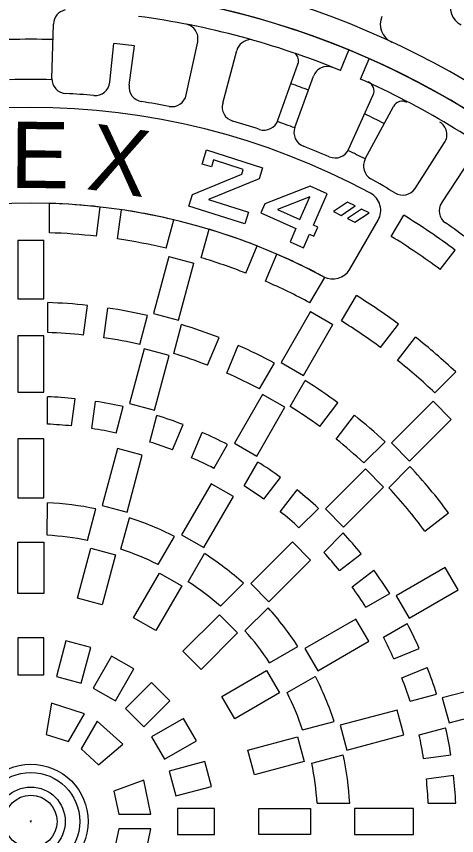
# Model space of a CAD drawing. Extents: x -7.1 to 10, y -5 to 6.
# Drawn here: x -4.588 to -4.121, y 0.707 to 1.576 of the extents above; entities that cross this region are included whole.
import ezdxf

# ---------------------------------------------------------------- set-up
doc = ezdxf.new("R2010")
doc.units = 0
doc.layers.add('Level 1', color=7, linetype='Continuous')

# ---------------------------------------------------------------- blocks, each defined once
blk = doc.blocks.new('CRAN')
at = {"layer": 'Level 1'}
for p, q in [((-3.652, 6.599), (-1.391, 7.083)), ((-3.232, 4.178), (-1.568, 4.4)), ((-1.568, 4.4), (-1.47, 3.52)), ((-3.114, 3.352), (-1.47, 3.52)), ((-2.949, 0.9), (-0.638, 0.965)), ((-2.949, -0.892), (-0.638, -0.957)), ((-3.114, -3.345), (-1.471, -3.52)), ((-1.568, -4.392), (-1.47, -3.512)), ((-3.232, -4.17), (-1.568, -4.392)), ((-3.652, -6.592), (-1.391, -7.076))]:
    blk.add_line(p, q, dxfattribs=at)
for centre, radius, start, end in [((-1.26, 6.472), 0.625, 11.0144, 102.0722), ((-3.521, 5.988), 0.625, 102.0722, 190.9368), ((-34.491, 0.004), 30.918, 8.7409, 10.9368), ((-3.315, 4.797), 0.625, 188.7409, 277.6056), ((-3.048, 2.731), 0.625, 96.0776, 184.9422), ((-34.473, 0.013), 30.918, 2.7463, 4.9422), ((-2.967, 1.524), 0.625, 182.7463, 271.611), ((-0.656, 1.589), 0.625, 271.611, 348.8242), ((-2.967, -1.517), 0.625, 88.389, 177.2537), ((-0.656, -1.582), 0.625, 11.1758, 88.389), ((-34.473, -0.006), 30.918, 355.0578, 357.2537), ((-3.048, -2.723), 0.625, 175.0578, 263.9224), ((-3.315, -4.79), 0.625, 82.3944, 171.2591), ((-34.491, 0.004), 30.918, 349.0632, 351.2591), ((-3.521, -5.981), 0.625, 169.0632, 257.9278), ((-1.26, -6.464), 0.625, 257.9278, 348.9856)]:
    blk.add_arc(centre, radius, start, end, dxfattribs=at)

msp = doc.modelspace()

# ---------------------------------------------------------------- linework, layer by layer
at = {"layer": 'Level 1'}
for p, q in [((-4.55009, 1.51031), (-4.54846, 1.56809)), ((-4.4076, 1.49275), (-4.39551, 1.54927)), ((-4.48878, 1.50619), (-4.48441, 1.54728)), ((-4.46259, 1.54485), (-4.48459, 1.5473)), ((-4.46814, 1.50325), (-4.46259, 1.54485)), ((-4.36899, 1.48413), (-4.35397, 1.53995)), ((-4.24409, 1.51875), (-4.23516, 1.54042)), ((-4.22297, 1.50971), (-4.21346, 1.53114)), ((-4.31032, 1.46587), (-4.28915, 1.52559)), ((-4.29245, 1.45828), (-4.27271, 1.51261)), ((-4.23555, 1.43507), (-4.20935, 1.49276)), ((-4.21784, 1.42485), (-4.18778, 1.48062)), ((-4.16493, 1.39361), (-4.13363, 1.4422)), ((-4.55279, 1.34647), (-4.5525, 1.37772)), ((-4.50287, 1.34289), (-4.49879, 1.37388)), ((-4.48041, 1.33996), (-4.47622, 1.37093)), ((-4.19015, 1.34266), (-4.17692, 1.3651)), ((-4.42893, 1.33007), (-4.42076, 1.36025)), ((-4.23411, 1.30787), (-4.20415, 1.35976)), ((-4.39178, 1.32008), (-4.38341, 1.3502)), ((-4.58616, 1.33881), (-4.58616, 1.2763)), ((-4.58616, 1.33881), (-4.55882, 1.33881)), ((-4.55882, 1.2763), (-4.55882, 1.33881)), ((-4.55882, 1.2763), (-4.55882, 1.33881)), ((-4.34449, 1.3037), (-4.33253, 1.33258)), ((-4.32355, 1.29506), (-4.31149, 1.32389)), ((-4.13823, 1.30753), (-4.12238, 1.32819)), ((-4.426, 1.32133), (-4.44218, 1.26094)), ((-4.426, 1.32133), (-4.39958, 1.31425)), ((-4.41577, 1.25386), (-4.39958, 1.31425)), ((-4.41577, 1.25386), (-4.39958, 1.31425)), ((-4.27638, 1.27218), (-4.26068, 1.29922)), ((-4.24309, 1.25293), (-4.22721, 1.27985)), ((-4.58616, 1.2763), (-4.55882, 1.2763)), ((-4.55457, 1.24066), (-4.5545, 1.27245)), ((-4.51666, 1.23796), (-4.51251, 1.26947)), ((-4.49496, 1.23515), (-4.49082, 1.26665)), ((-4.44218, 1.26094), (-4.41577, 1.25386)), ((-4.27581, 1.26298), (-4.30707, 1.20884)), ((-4.27581, 1.26298), (-4.25213, 1.24931)), ((-4.45683, 1.22792), (-4.44861, 1.25863)), ((-4.42088, 1.21834), (-4.41259, 1.24903)), ((-4.28339, 1.19517), (-4.25213, 1.24931)), ((-4.28339, 1.19517), (-4.25213, 1.24931)), ((-4.20164, 1.22486), (-4.18262, 1.24966)), ((-4.58616, 1.23722), (-4.58616, 1.1773)), ((-4.55882, 1.23722), (-4.58616, 1.23722)), ((-4.55882, 1.1773), (-4.55882, 1.23722)), ((-4.38496, 1.20592), (-4.3728, 1.23528)), ((-4.18366, 1.2111), (-4.16455, 1.23582)), ((-4.36474, 1.19759), (-4.35258, 1.22695)), ((-4.45229, 1.2232), (-4.4678, 1.16532)), ((-4.42588, 1.21612), (-4.45229, 1.2232)), ((-4.44139, 1.15824), (-4.42588, 1.21612)), ((-4.30707, 1.20884), (-4.28339, 1.19517)), ((-4.32978, 1.18074), (-4.31388, 1.20828)), ((-4.14402, 1.17679), (-4.12185, 1.19884)), ((-4.29753, 1.16218), (-4.28158, 1.18968)), ((-4.58616, 1.1773), (-4.55882, 1.1773)), ((-4.32661, 1.175), (-4.35657, 1.12311)), ((-4.30293, 1.16133), (-4.32661, 1.175)), ((-4.55477, 1.14338), (-4.55471, 1.17251)), ((-4.52935, 1.14155), (-4.52555, 1.17041)), ((-4.50766, 1.13875), (-4.50386, 1.1676)), ((-4.4678, 1.16532), (-4.44139, 1.15824)), ((-4.26605, 1.14089), (-4.2467, 1.1661)), ((-4.14585, 1.16776), (-4.19005, 1.12355)), ((-4.14585, 1.16776), (-4.12651, 1.14842)), ((-4.48202, 1.13394), (-4.47448, 1.16208)), ((-4.33289, 1.10944), (-4.30293, 1.16133)), ((-4.44625, 1.12443), (-4.43866, 1.15255)), ((-4.24867, 1.12761), (-4.22932, 1.15282)), ((-4.17072, 1.10421), (-4.12651, 1.14842)), ((-4.17072, 1.10421), (-4.12651, 1.14842)), ((-4.42218, 1.11608), (-4.41104, 1.14297)), ((-4.40195, 1.10776), (-4.39081, 1.13465)), ((-4.58616, 1.1278), (-4.58616, 1.06526)), ((-4.55882, 1.1278), (-4.58616, 1.1278)), ((-4.55882, 1.06526), (-4.55882, 1.1278)), ((-4.37842, 1.09648), (-4.36386, 1.12171)), ((-4.35657, 1.12311), (-4.33289, 1.10944)), ((-4.21926, 1.10228), (-4.19678, 1.12476)), ((-4.19005, 1.12355), (-4.17072, 1.10421)), ((-4.48061, 1.1175), (-4.4968, 1.05709)), ((-4.4542, 1.11042), (-4.48061, 1.1175)), ((-4.47039, 1.05001), (-4.4542, 1.11042)), ((-4.34634, 1.07804), (-4.33173, 1.10323)), ((-4.21768, 1.09592), (-4.26005, 1.05355)), ((-4.19835, 1.07658), (-4.21768, 1.09592)), ((-4.19291, 1.07601), (-4.17039, 1.09844)), ((-4.32525, 1.06374), (-4.30753, 1.08683)), ((-4.38132, 1.08024), (-4.41259, 1.02607)), ((-4.35764, 1.06656), (-4.38132, 1.08024)), ((-4.30786, 1.05047), (-4.29014, 1.07356)), ((-4.24072, 1.03421), (-4.19835, 1.07658)), ((-4.58616, 1.06526), (-4.55882, 1.06526)), ((-4.38891, 1.0124), (-4.35764, 1.06656)), ((-4.55501, 1.02552), (-4.55494, 1.0601)), ((-4.51253, 1.02006), (-4.50358, 1.05348)), ((-4.4968, 1.05709), (-4.47039, 1.05001)), ((-4.28805, 1.03349), (-4.26746, 1.05408)), ((-4.26005, 1.05355), (-4.24072, 1.03421)), ((-4.47699, 1.01065), (-4.46797, 1.04403)), ((-4.15466, 1.02997), (-4.12945, 1.04931)), ((-4.41259, 1.02607), (-4.38891, 1.0124)), ((-4.26184, 1.00737), (-4.2412, 1.02792)), ((-4.58616, 0.96358), (-4.58616, 1.01834)), ((-4.58616, 1.01834), (-4.55882, 1.01834)), ((-4.55882, 1.01834), (-4.55882, 0.96358)), ((-4.43738, 0.99437), (-4.42008, 1.02434)), ((-4.29506, 1.01854), (-4.33928, 0.97432)), ((-4.27572, 0.99921), (-4.29506, 1.01854)), ((-4.52311, 0.95888), (-4.50894, 1.01177)), ((-4.50894, 1.01177), (-4.48253, 1.00469)), ((-4.48253, 1.00469), (-4.4967, 0.9518)), ((-4.40548, 0.97609), (-4.38813, 1.006)), ((-4.24517, 0.98809), (-4.22207, 1.00582)), ((-4.31995, 0.95499), (-4.27572, 0.99921)), ((-4.13294, 0.99134), (-4.18483, 0.96138)), ((-4.11927, 0.96766), (-4.13294, 0.99134)), ((-4.46343, 0.93802), (-4.43605, 0.98544)), ((-4.43605, 0.98544), (-4.41237, 0.97177)), ((-4.2318, 0.97077), (-4.20871, 0.98849)), ((-4.37143, 0.95012), (-4.34696, 0.97458)), ((-4.33928, 0.97432), (-4.31995, 0.95499)), ((-4.41237, 0.97177), (-4.43975, 0.92435)), ((-4.17116, 0.9377), (-4.11927, 0.96766)), ((-4.55882, 0.96358), (-4.58616, 0.96358)), ((-4.4967, 0.9518), (-4.52311, 0.95888)), ((-4.21707, 0.94925), (-4.19184, 0.96381)), ((-4.18483, 0.96138), (-4.17116, 0.9377)), ((-4.34535, 0.9242), (-4.32085, 0.9486)), ((-4.41118, 0.90242), (-4.37246, 0.94114)), ((-4.37246, 0.94114), (-4.35312, 0.92181)), ((-4.43975, 0.92435), (-4.46343, 0.93802)), ((-4.2277, 0.93663), (-4.28187, 0.90536)), ((-4.21403, 0.91295), (-4.2277, 0.93663)), ((-4.19851, 0.91723), (-4.17326, 0.93174)), ((-4.35312, 0.92181), (-4.39184, 0.88309)), ((-4.55882, 0.91661), (-4.58616, 0.91661)), ((-4.58616, 0.91661), (-4.58616, 0.87743)), ((-4.55882, 0.87743), (-4.55882, 0.91661)), ((-4.53527, 0.91351), (-4.54541, 0.87566)), ((-4.50886, 0.90643), (-4.53527, 0.91351)), ((-4.26819, 0.88168), (-4.21403, 0.91295)), ((-4.519, 0.86859), (-4.50886, 0.90643)), ((-4.31918, 0.8903), (-4.28922, 0.90759)), ((-4.28187, 0.90536), (-4.26819, 0.88168)), ((-4.18739, 0.8943), (-4.1605, 0.90545)), ((-4.18739, 0.8943), (-4.1605, 0.90544)), ((-4.48691, 0.89734), (-4.50651, 0.86341)), ((-4.46323, 0.88367), (-4.48691, 0.89734)), ((-4.39184, 0.88309), (-4.41118, 0.90242)), ((-4.48283, 0.84974), (-4.46323, 0.88367)), ((-4.36992, 0.85452), (-4.3225, 0.8819)), ((-4.3225, 0.8819), (-4.30883, 0.85822)), ((-4.17897, 0.87411), (-4.15208, 0.88525)), ((-4.58616, 0.87743), (-4.55882, 0.87743)), ((-4.54541, 0.87566), (-4.519, 0.86859)), ((-4.3007, 0.85851), (-4.27072, 0.87574)), ((-4.50651, 0.86341), (-4.48283, 0.84974)), ((-4.44439, 0.86921), (-4.4721, 0.84151)), ((-4.42506, 0.84988), (-4.44439, 0.86921)), ((-4.07815, 0.86839), (-4.13603, 0.85288)), ((-4.35625, 0.83084), (-4.36992, 0.85452)), ((-4.30883, 0.85822), (-4.35625, 0.83084)), ((-4.17031, 0.84951), (-4.14217, 0.85705)), ((-4.13603, 0.85288), (-4.12895, 0.82647)), ((-4.55038, 0.84745), (-4.55624, 0.81411)), ((-4.51557, 0.83598), (-4.55038, 0.84745)), ((-4.45276, 0.82217), (-4.42506, 0.84988)), ((-4.53255, 0.80659), (-4.51557, 0.83598)), ((-4.4721, 0.84151), (-4.45276, 0.82217)), ((-4.18384, 0.84007), (-4.24426, 0.82388)), ((-4.17677, 0.81366), (-4.18384, 0.84007)), ((-4.12895, 0.82647), (-4.07107, 0.84198)), ((-4.50204, 0.82817), (-4.51901, 0.79878)), ((-4.47471, 0.80377), (-4.50204, 0.82817)), ((-4.4106, 0.83103), (-4.44453, 0.81144)), ((-4.39692, 0.80735), (-4.4106, 0.83103)), ((-4.28419, 0.81899), (-4.25077, 0.82795)), ((-4.24426, 0.82388), (-4.23718, 0.79747)), ((-4.16066, 0.81378), (-4.13252, 0.82126)), ((-4.55624, 0.81411), (-4.53255, 0.80659)), ((-4.44453, 0.81144), (-4.43086, 0.78776)), ((-4.34247, 0.79757), (-4.28957, 0.81174)), ((-4.28957, 0.81174), (-4.2825, 0.78533)), ((-4.23718, 0.79747), (-4.17677, 0.81366)), ((-4.50065, 0.78201), (-4.47471, 0.80377)), ((-4.43086, 0.78776), (-4.39692, 0.80735)), ((-4.51901, 0.79878), (-4.50065, 0.78201)), ((-4.33539, 0.77115), (-4.34247, 0.79757)), ((-4.27457, 0.78351), (-4.24115, 0.79239)), ((-4.15586, 0.78875), (-4.127, 0.79255)), ((-4.38784, 0.78541), (-4.42568, 0.77527)), ((-4.38076, 0.759), (-4.38784, 0.78541)), ((-4.2825, 0.78533), (-4.33539, 0.77115)), ((-4.42568, 0.77527), (-4.41861, 0.74886)), ((-4.4526, 0.76546), (-4.48441, 0.75387)), ((-4.44513, 0.72959), (-4.4526, 0.76546)), ((-4.15295, 0.76707), (-4.12409, 0.77087)), ((-4.41861, 0.74886), (-4.38076, 0.759)), ((-4.48441, 0.75387), (-4.47907, 0.72959)), ((-4.26886, 0.74106), (-4.23426, 0.74106)), ((-4.15095, 0.74106), (-4.12182, 0.74106)), ((-4.41684, 0.73545), (-4.41684, 0.70811)), ((-4.37766, 0.73545), (-4.41684, 0.73545)), ((-4.37766, 0.70811), (-4.37766, 0.73545)), ((-4.33069, 0.70811), (-4.33069, 0.73545)), ((-4.33069, 0.73545), (-4.27593, 0.73545)), ((-4.27593, 0.73545), (-4.27593, 0.70811)), ((-4.22901, 0.73545), (-4.22901, 0.70811)), ((-4.16647, 0.73545), (-4.22901, 0.73545)), ((-4.16647, 0.70811), (-4.16647, 0.73545)), ((-4.57205, 0.72293), (-4.57292, 0.7213)), ((-4.57205, 0.72065), (-4.57292, 0.72228)), ((-4.57249, 0.72178), (-4.57249, 0.72178)), ((-4.47907, 0.72959), (-4.44513, 0.72959)), ((-4.47907, 0.71396), (-4.48441, 0.68968)), ((-4.44513, 0.71396), (-4.47907, 0.71396)), ((-4.4526, 0.67809), (-4.44513, 0.71396)), ((-4.41684, 0.70811), (-4.37766, 0.70811)), ((-4.27593, 0.70811), (-4.33069, 0.70811)), ((-4.22901, 0.70811), (-4.16647, 0.70811))]:
    msp.add_line(p, q, dxfattribs=at)
for points in [[(-4.37859, 1.4238), (-4.38095, 1.41636), (-4.39088, 1.4195), (-4.38616, 1.4344), (-4.32658, 1.41552), (-4.33025, 1.40391), (-4.38399, 1.38181), (-4.34152, 1.36835), (-4.34545, 1.35594), (-4.40503, 1.37482), (-4.4011, 1.38723), (-4.34875, 1.40889), (-4.34718, 1.41385)], [(-4.28324, 1.3306), (-4.27693, 1.3449), (-4.27217, 1.3428), (-4.26797, 1.35233), (-4.27273, 1.35443), (-4.25803, 1.38779), (-4.27628, 1.39583), (-4.32434, 1.37718), (-4.32854, 1.36764), (-4.29123, 1.3512), (-4.29753, 1.3369)], [(-4.27653, 1.38456), (-4.31086, 1.37124), (-4.28703, 1.36073)], [(-4.24346, 1.36498), (-4.22845, 1.37499), (-4.23654, 1.37899), (-4.25155, 1.36898)], [(-4.22866, 1.35768), (-4.21365, 1.36769), (-4.22173, 1.37169), (-4.23674, 1.36168)]]:
    msp.add_lwpolyline(points, close=True, dxfattribs=at)
for radius in [0.0608, 0.05199, 0.03649, 0.02784]:
    msp.add_circle((-4.57249, 0.72178), radius, dxfattribs=at)
for centre, radius, start, end in [((-4.57265, 0.72181), 1.15162, 195.07169, 189.12267), ((-4.57249, 0.72178), 0.91146, 12.31851, 171.9696), ((-4.57249, 0.72178), 0.88542, 5.66744, 175.39465), ((-4.57249, 0.72178), 0.88542, 5.66744, 126.73442), ((-4.10653, 1.58556), 0.02083, 153.8952, 242.69061), ((-4.53285, 1.56765), 0.01563, 101.17582, 178.38902), ((-4.57249, 0.72178), 0.86198, 67.60558, 82.39442), ((-4.18097, 1.56787), 0.02083, 156.4401, 245.16801), ((-4.41079, 1.55254), 0.01563, 347.92782, 78.98565), ((-4.57249, 0.72178), 0.83011, 88.3735, 91.6265), ((-4.33889, 1.53589), 0.01562, 90.24421, 164.94218), ((-4.29896, 1.52907), 0.01042, 340.47558, 48.37664), ((-4.25802, 1.50727), 0.01562, 68.97738, 160.03521), ((-4.57249, 0.72178), 0.78745, 88.36809, 91.63191), ((-4.53447, 1.50987), 0.01563, 178.38902, 267.25366), ((-4.50432, 1.50785), 0.01563, 265.05778, 353.92242), ((-4.57249, 0.72178), 0.83011, 69.22478, 70.58518), ((-4.57249, 0.72178), 0.86198, 51.95558, 66.07801), ((-4.21883, 1.49706), 0.01042, 335.56861, 66.27812), ((-4.45266, 1.50118), 0.01563, 172.39442, 261.25906), ((-4.57225, 0.72221), 0.77294, 85.05778, 87.25366), ((-4.42288, 1.49602), 0.01563, 259.06318, 347.92782), ((-4.57249, 0.72178), 0.75781, 61.61988, 118.38012), ((-4.57249, 0.72178), 0.77294, 79.06318, 81.25906), ((-4.3539, 1.48008), 0.01562, 164.94218, 253.80682), ((-4.17861, 1.47568), 0.01042, 60.96915, 151.67866), ((-4.57249, 0.72178), 0.83011, 63.15242, 64.7577), ((-4.57381, 0.7228), 0.77294, 71.61094, 73.80682), ((-4.32505, 1.47109), 0.01562, 251.61094, 340.47558), ((-4.57249, 0.72178), 0.78745, 69.1803, 70.59091), ((-4.14676, 1.45066), 0.01562, 327.21206, 58.26989), ((-4.27776, 1.45295), 0.01562, 160.03521, 248.89985), ((-4.56164, 0.71725), 0.77294, 66.70397, 68.89985), ((-4.24978, 1.44153), 0.01562, 246.70397, 335.56861), ((-4.57249, 0.72178), 0.78745, 63.23227, 64.71842), ((-4.20409, 1.41743), 0.01562, 151.67866, 240.5433), ((-4.59188, 0.73081), 0.77294, 58.34742, 60.5433), ((-4.17806, 1.40207), 0.01562, 238.34742, 327.21206), ((-4.22219, 1.37018), 0.02083, 330, 61.61988), ((-4.57249, 0.72178), 0.65625, 61.76323, 118.23677), ((-4.57249, 0.72178), 0.65625, 83.55203, 88.25436), ((-4.57249, 0.72178), 0.65625, 76.63169, 81.56459), ((-4.57249, 0.72178), 0.75521, 53.41505, 58.41284), ((-4.57249, 0.72178), 0.65625, 68.55203, 73.25436), ((-4.57249, 0.72178), 0.625, 83.60431, 88.19389), ((-4.57249, 0.72178), 0.625, 76.72031, 81.52788), ((-4.57249, 0.72178), 0.72917, 53.44749, 58.3753), ((-4.57249, 0.72178), 0.65625, 61.63169, 66.56459), ((-4.57249, 0.72178), 0.625, 68.60431, 73.19389), ((-4.25215, 1.31829), 0.02083, 241.76323, 330), ((-4.57249, 0.72178), 0.625, 61.72031, 66.52788), ((-4.57249, 0.72178), 0.65625, 53.55203, 58.25436), ((-4.57249, 0.72178), 0.55096, 83.75013, 88.12895), ((-4.57249, 0.72178), 0.55096, 77.00587, 81.47515), ((-4.57249, 0.72178), 0.625, 53.60431, 58.19389), ((-4.57249, 0.72178), 0.55096, 68.75013, 73.12895), ((-4.57249, 0.72178), 0.51919, 83.82664, 88.02167), ((-4.57249, 0.72178), 0.51919, 77.12867, 81.41243), ((-4.57249, 0.72178), 0.65625, 46.63169, 51.56459), ((-4.57249, 0.72178), 0.55096, 62.00587, 66.47515), ((-4.57249, 0.72178), 0.51919, 68.82664, 73.02167), ((-4.57249, 0.72178), 0.625, 46.72031, 51.52788), ((-4.57249, 0.72178), 0.51919, 62.12867, 66.41243), ((-4.57249, 0.72178), 0.55096, 53.75013, 58.12895), ((-4.57249, 0.72178), 0.45108, 84.02701, 87.74069), ((-4.57249, 0.72178), 0.45108, 77.45028, 81.24818), ((-4.57249, 0.72178), 0.51919, 53.82664, 58.02167), ((-4.57249, 0.72178), 0.45108, 69.02701, 72.74069), ((-4.57249, 0.72178), 0.55096, 47.00587, 51.47515), ((-4.57249, 0.72178), 0.42198, 84.13234, 87.59298), ((-4.57249, 0.72178), 0.42198, 77.61937, 81.16184), ((-4.57249, 0.72178), 0.45108, 62.45028, 66.24818), ((-4.57249, 0.72178), 0.42198, 69.13234, 72.59298), ((-4.57249, 0.72178), 0.51919, 47.12867, 51.41243), ((-4.57249, 0.72178), 0.42198, 62.61937, 66.16184), ((-4.57249, 0.72178), 0.45108, 54.02701, 57.74069), ((-4.57249, 0.72178), 0.55096, 36.47515, 43.12895), ((-4.57249, 0.72178), 0.42198, 54.13234, 57.59298), ((-4.57249, 0.72178), 0.45108, 47.45028, 51.24818), ((-4.57249, 0.72178), 0.51919, 36.41243, 43.02167), ((-4.57249, 0.72178), 0.33878, 78.26326, 87.03051), ((-4.57249, 0.72178), 0.33878, 63.26326, 72.03051), ((-4.57249, 0.72178), 0.42198, 47.61937, 51.16184), ((-4.57249, 0.72178), 0.45108, 39.02701, 42.74069), ((-4.57249, 0.72178), 0.30425, 78.63416, 86.70655), ((-4.57249, 0.72178), 0.30425, 63.63416, 71.70655), ((-4.57249, 0.72178), 0.33878, 48.26326, 57.03051), ((-4.57249, 0.72178), 0.42198, 39.13234, 42.59298), ((-4.57249, 0.72178), 0.45108, 32.45028, 36.24818), ((-4.57249, 0.72178), 0.30425, 48.63416, 56.70655), ((-4.57249, 0.72178), 0.42198, 32.61937, 36.16184), ((-4.57249, 0.72178), 0.33878, 33.26326, 42.03051), ((-4.57249, 0.72178), 0.45108, 24.02701, 27.74069), ((-4.57249, 0.72178), 0.30425, 33.63416, 41.70655), ((-4.57249, 0.72178), 0.42198, 24.13234, 27.59298), ((-4.57249, 0.72178), 0.45108, 17.45028, 21.24818), ((-4.57249, 0.72178), 0.33878, 18.26326, 27.03051), ((-4.57249, 0.72178), 0.42198, 17.61937, 21.16184), ((-4.57249, 0.72178), 0.30425, 18.63416, 26.70655), ((-4.57249, 0.72178), 0.45108, 9.02701, 12.74069), ((-4.57249, 0.72178), 0.42198, 9.13234, 12.59298), ((-4.57249, 0.72178), 0.33878, 3.26326, 12.03051), ((-4.57249, 0.72178), 0.30425, 3.63416, 11.70655), ((-4.57249, 0.72178), 0.42198, 2.61937, 6.16184), ((-4.57249, 0.72178), 0.45108, 2.45028, 6.24818)]:
    msp.add_arc(centre, radius, start, end, dxfattribs=at)

# ---------------------------------------------------------------- block references
at = {"layer": 'Level 1', "xscale": 0.025, "yscale": 0.025000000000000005, "rotation": 44.350000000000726}
msp.add_blockref('CRAN', (-3.9561, 1.32433), dxfattribs=at)

# ---------------------------------------------------------------- texts
at = {"layer": 'Level 1'}
for s, rotation, p in [('E', 359.49724, (-4.59451, 1.3942)), ('X', 351.96239, (-4.51476, 1.39299))]:
    msp.add_text(s, height=0.07031, rotation=rotation, dxfattribs=at).set_placement(p)

doc.saveas('drawing.dxf')
